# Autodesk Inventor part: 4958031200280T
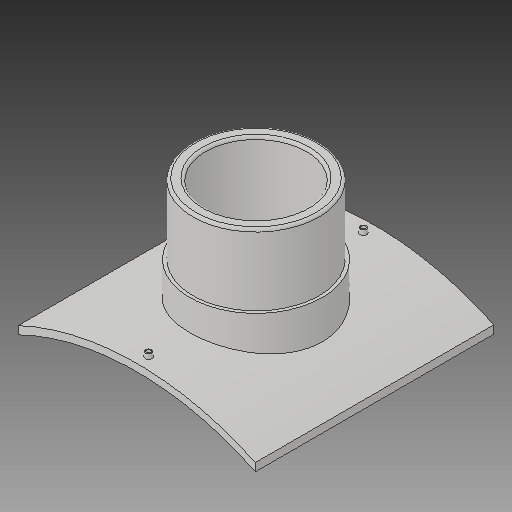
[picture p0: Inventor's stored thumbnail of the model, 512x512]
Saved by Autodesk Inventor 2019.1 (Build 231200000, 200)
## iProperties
Created: 2017-10
Part Number: 4958031200280T
Material: Generic
Description: PLASSON BRANCH SADDLE  1200x280
Document SubType Name: Modeling
Designer: KIM
Mass: 2754.05 g
Surface Area: 3037.44 cm^2
Volume: 2754.05 cm^3
Density: 1 g/cm^3
Appearance: Default
Author: KIM
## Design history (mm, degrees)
derived "495803.ipt"
feature "Solid1::495803.ipt"
tag "TaggingFeature1"
body "Solid1"
other parameters: "d1" = 16, "d2" = 527, "d4" = 0, "d12" = 625.6, "d13" = 14, "d14" = 238.5, "d16" = 5 deg, "d18" = 4, "d19" = 14, "d20" = 0, "d21" = 3, "d22" = 0, "d23" = 841, "d24" = 294, "d25" = 16, "d26" = 224, "d28" = 0, "d29" = 9.6, "d31" = 0, "d32" = 112.5, "d33" = 0, "d34" = 12, "d37" = 157.5, "d38" = 0, "d39" = 6, "B_" = 527, "H_" = 225, "x_" = 16, "D_" = 16
